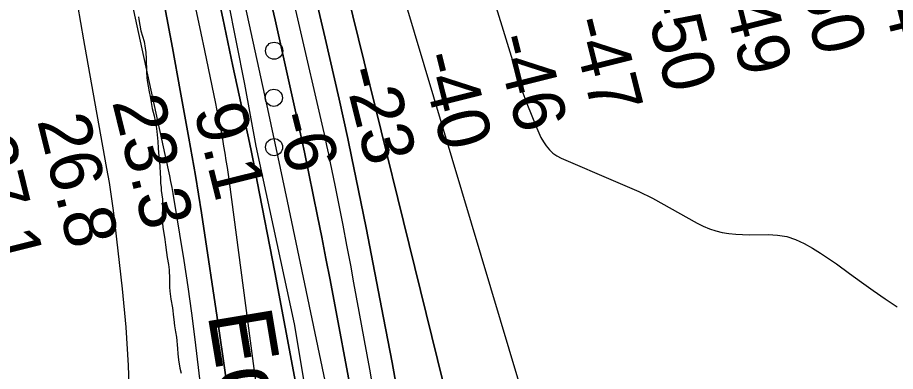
# Model space of a CAD drawing. Extents: x 3250478 to 3288318, y 788638 to 816472.
# Drawn here: x 3274100 to 3275236, y 806350 to 806808 of the extents above; entities that cross this region are included whole.
import ezdxf

# ---------------------------------------------------------------- set-up
doc = ezdxf.new("R2010")
doc.units = 0
for name, color, linetype in [('V-ANNO-SYMB', 7, 'Continuous'), ('V-RIVR-EDGE', 7, 'Continuous'), ('V-RIVR-IDEN', 7, 'Continuous'), ('V-RIVR-RANG', 7, 'Continuous'), ('V-SITE-VEGE', 7, 'Continuous'), ('V-TOPO-DPTH', 7, 'Continuous'), ('V-TOPO-MAJR', 7, 'Continuous'), ('V-TOPO-MINR', 7, 'Continuous'), ('V-TOPO-WATR', 7, 'Continuous')]:
    doc.layers.add(name, color=color, linetype=linetype)

msp = doc.modelspace()

# ---------------------------------------------------------------- linework, layer by layer
at = {"layer": 'V-ANNO-SYMB'}
for centre in [(3274431.8095558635, 806765.4957831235), (3274431.418346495, 806704.615252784), (3274431.7732697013, 806640.7464983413)]:
    msp.add_circle(centre, 11.10590807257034, dxfattribs=at)
at = {"layer": 'V-RIVR-EDGE'}
msp.add_lwpolyline([(3274372.0164002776, 806831.2774582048), (3274393.4804442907, 806722.1199082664), (3274408.0616774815, 806642.1028829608), (3274457.9155695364, 806412.0343195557), (3274469.051635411, 806345.0661887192), (3274504.142647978, 806121.5543174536), (3274513.578701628, 806070.2388409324), (3274547.7466196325, 805824.9952929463), (3274554.1711076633, 805786.2929595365), (3274589.6376810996, 805538.8728044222), (3274595.179918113, 805494.9565023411), (3274635.0040051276, 805251.8723642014), (3274642.658359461, 805183.174125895), (3274676.309913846, 804904.8962366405), (3274682.3050995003, 804868.3683606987), (3274707.6935005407, 804588.3721871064)], dxfattribs=at)
at = {"layer": 'V-SITE-VEGE'}
msp.add_lwpolyline([(3274256.3850000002, 806809.282), (3274256.786, 806806.054), (3274259.508, 806791.061), (3274263.6350000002, 806777.421), (3274265.091, 806768.889), (3274265.681, 806763.359), (3274266.218, 806754.844), (3274266.615, 806738.282), (3274267.166, 806730.454), (3274267.973, 806724.232), (3274270.06, 806712.237), (3274271.3310000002, 806706.237), (3274274.041, 806690.5530000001), (3274276.4, 806681.085), (3274277.662, 806674.394), (3274279.151, 806667.701), (3274279.947, 806660.787), (3274281.098, 806648.123), (3274281.6350000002, 806639.376), (3274282.227, 806633.846), (3274283.98, 806616.112), (3274284.267, 806606.448), (3274284.631, 806601.154), (3274284.965, 806594.0210000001), (3274285.555, 806588.491), (3274285.717, 806584.579), (3274287.355, 806573.285), (3274287.486, 806567.763), (3274287.111, 806546.8470000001), (3274287.631, 806537.18), (3274290.3310000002, 806521.0380000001), (3274291.127, 806514.126), (3274292.559, 806504.214), (3274293.593, 806497.756), (3274295.272, 806488.76), (3274296.073, 806482.079), (3274296.5500000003, 806470.112), (3274296.591, 806459.537), (3274296.727, 806454.247), (3274297.921, 806443.878), (3274300.247, 806432.569), (3274301.414, 806420.5920000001), (3274302.051, 806417.5920000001), (3274303.057, 806409.527), (3274304.292, 806401.457), (3274305.553, 806394.767), (3274306.899, 806380.027), (3274307.235, 806373.123), (3274308.019, 806365.5210000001), (3274309.666, 806354.685), (3274311.39, 806348.218)], dxfattribs=at)
at = {"layer": 'V-TOPO-DPTH'}
for points in [[(3272896.8718829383, 811666.7885982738), (3273467.3050510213, 810068.0688245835), (3273725.425261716, 809243.5940511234), (3273978.688410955, 808646.7703251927), (3274258.488397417, 807822.2419438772), (3274387.5351008, 807404.5846132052), (3274650.472167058, 806336.1989603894), (3274951.6704880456, 805397.7981484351), (3275222.5651054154, 804691.4067671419)], [(3275222.5651054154, 804691.4067671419), (3274951.6704880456, 805397.7981484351), (3274650.472167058, 806336.1989603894), (3274387.5351008, 807404.5846132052), (3274258.488397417, 807822.2419438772), (3273978.688410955, 808646.7703251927), (3273725.425261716, 809243.5940511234), (3273467.3050510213, 810068.0688245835), (3272896.8718829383, 811666.7885982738)], [(3274617.4222593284, 805491.1386361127), (3274604.2925982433, 805560.98414393), (3274590.6944715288, 805630.7440241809), (3274541.090595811, 805878.5779743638), (3274536.753836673, 805900.6834834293), (3274532.52971438, 805922.8100506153), (3274528.474547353, 805944.9682049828), (3274524.5320171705, 805967.1474174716), (3274485.1562987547, 806193.672837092), (3274472.5268671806, 806265.1076904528), (3274459.6231666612, 806336.4921489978), (3274446.3080627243, 806407.8010153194), (3274432.718689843, 806479.0594868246), (3274410.000424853, 806596.348323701), (3274407.5280961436, 806608.917167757), (3274405.0072768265, 806621.4761325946), (3274402.4137216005, 806634.0202786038), (3274399.7716757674, 806646.5545453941), (3274378.5716780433, 806745.7061613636), (3274365.266387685, 806807.8030393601), (3274351.9252642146, 806869.892201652)], [(3274351.9252642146, 806869.892201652), (3274365.266387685, 806807.8030393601), (3274378.5716780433, 806745.7061613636), (3274399.7716757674, 806646.5545453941), (3274402.4137216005, 806634.0202786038), (3274405.0072768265, 806621.4761325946), (3274407.5280961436, 806608.917167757), (3274410.000424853, 806596.348323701), (3274432.718689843, 806479.0594868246), (3274446.3080627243, 806407.8010153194), (3274459.6231666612, 806336.4921489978), (3274472.5268671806, 806265.1076904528), (3274485.1562987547, 806193.672837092), (3274524.5320171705, 805967.1474174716), (3274528.474547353, 805944.9682049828), (3274532.52971438, 805922.8100506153), (3274536.753836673, 805900.6834834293), (3274541.090595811, 805878.5779743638), (3274590.6944715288, 805630.7440241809), (3274604.2925982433, 805560.98414393), (3274617.4222593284, 805491.1386361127)], [(3274688.1484999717, 805434.1228253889), (3274676.465678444, 805507.2707436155), (3274664.4258522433, 805580.3607487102), (3274652.1480229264, 805653.4121450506), (3274608.4767440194, 805909.4249769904), (3274606.0971900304, 805923.1733139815), (3274603.6732208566, 805936.9137044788), (3274601.1826289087, 805950.6421752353), (3274598.647621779, 805964.3626994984), (3274504.183789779, 806468.78976013), (3274498.939337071, 806496.4099469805), (3274493.602246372, 806524.0119793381), (3274488.126198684, 806551.5867799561), (3274482.557513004, 806579.1434260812), (3274476.8515547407, 806606.6719972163), (3274471.0552148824, 806634.1812916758), (3274465.1233026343, 806661.6616711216), (3274459.1010087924, 806689.1227738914), (3274452.270295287, 806719.9072703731), (3274442.7205471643, 806762.7361712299), (3274433.111722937, 806805.5517497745), (3274423.414284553, 806848.347344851)], [(3274423.414284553, 806848.347344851), (3274433.111722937, 806805.5517497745), (3274442.7205471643, 806762.7361712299), (3274452.270295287, 806719.9072703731), (3274459.1010087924, 806689.1227738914), (3274465.1233026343, 806661.6616711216), (3274471.0552148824, 806634.1812916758), (3274476.8515547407, 806606.6719972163), (3274482.557513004, 806579.1434260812), (3274488.126198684, 806551.5867799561), (3274493.602246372, 806524.0119793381), (3274498.939337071, 806496.4099469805), (3274504.183789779, 806468.78976013), (3274598.647621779, 805964.3626994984), (3274601.1826289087, 805950.6421752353), (3274603.6732208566, 805936.9137044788), (3274606.0971900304, 805923.1733139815), (3274608.4767440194, 805909.4249769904), (3274652.1480229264, 805653.4121450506), (3274664.4258522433, 805580.3607487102), (3274676.465678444, 805507.2707436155), (3274688.1484999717, 805434.1228253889)], [(3274482.658444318, 806846.3303660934), (3274497.777227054, 806781.6377285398), (3274515.898992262, 806702.7509565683), (3274521.609837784, 806677.4201953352), (3274527.18336579, 806652.0598389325), (3274532.5509175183, 806626.6550897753), (3274537.781151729, 806601.2207454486), (3274550.895423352, 806536.1087825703), (3274562.380969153, 806478.0585651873), (3274573.601449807, 806419.9580974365), (3274584.4243327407, 806361.7822541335), (3274594.9821505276, 806303.5561604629)], [(3274594.9821505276, 806303.5561604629), (3274584.4243327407, 806361.7822541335), (3274573.601449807, 806419.9580974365), (3274562.380969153, 806478.0585651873), (3274550.895423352, 806536.1087825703), (3274537.781151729, 806601.2207454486), (3274532.5509175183, 806626.6550897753), (3274527.18336579, 806652.0598389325), (3274521.609837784, 806677.4201953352), (3274515.898992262, 806702.7509565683), (3274497.777227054, 806781.6377285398), (3274482.658444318, 806846.3303660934)], [(3274600.483922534, 806832.0100823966), (3274859.3268003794, 805965.620046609)], [(3274600.483922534, 806832.0100823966), (3274859.3268003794, 805965.620046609)], [(3274478.8771368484, 805483.1582757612), (3274468.908506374, 805558.2114425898), (3274459.40646076, 805633.3287982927), (3274432.7241389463, 805852.4702170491), (3274429.869571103, 805875.8581771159), (3274427.0059573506, 805899.2450268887), (3274424.1287747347, 805922.6302112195), (3274421.2425462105, 805946.0142852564), (3274406.234731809, 806067.3173524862), (3274395.5255796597, 806151.3095590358), (3274384.4001715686, 806235.2450150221), (3274372.650379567, 806319.0953451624), (3274360.4843316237, 806402.8889247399), (3274337.7003442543, 806555.8091983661), (3274333.967639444, 806580.0158876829), (3274330.070924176, 806604.1952878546), (3274325.928193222, 806628.3337543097), (3274321.62145181, 806652.4449316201), (3274310.2803518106, 806714.1218491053), (3274300.174531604, 806769.0500017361), (3274290.061389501, 806823.9768055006)]]:
    msp.add_lwpolyline(points, dxfattribs=at)
at = {"layer": 'V-TOPO-MAJR'}
msp.add_lwpolyline([(3274653.0490446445, 807036.1317875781), (3274749.1714196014, 806725.0046189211), (3274751.4288745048, 806717.9909878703), (3274753.795132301, 806711.0156974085), (3274756.3245944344, 806704.09791783), (3274758.962859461, 806697.2184788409), (3274771.7233760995, 806665.0792478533), (3274774.3330273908, 806659.1308457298), (3274777.2116374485, 806653.3279504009), (3274780.4936856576, 806647.7433152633), (3274784.044692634, 806642.3041869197), (3274788.149218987, 806637.4056710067), (3274792.691259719, 806633.0457846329), (3274797.889572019, 806629.493842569), (3274803.5253986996, 806626.4805300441), (3274873.8457806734, 806596.1319161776), (3274879.850851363, 806593.550086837), (3274885.8606333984, 806590.979313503), (3274891.8774824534, 806588.4251241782), (3274897.899042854, 806585.8819908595), (3274903.877212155, 806583.250712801), (3274909.7929705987, 806580.4911715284), (3274915.6151127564, 806577.5392354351), (3274921.374844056, 806574.4590361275), (3274979.4019049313, 806542.1927834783), (3274987.202726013, 806538.3362342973), (3274995.1926584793, 806535.0024433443), (3275003.466258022, 806532.452789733), (3275011.9289689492, 806530.4258943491), (3275020.559471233, 806529.0603622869), (3275029.2202377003, 806528.039723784), (3275037.926400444, 806527.5364256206), (3275046.662827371, 806527.3780210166), (3275071.240764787, 806527.6653365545), (3275083.397129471, 806526.8684873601), (3275095.2592614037, 806524.8818654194), (3275106.6800442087, 806521.1105843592), (3275117.8065942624, 806516.1495305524), (3275128.562964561, 806510.0303936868), (3275139.136987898, 806503.6238546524), (3275149.437490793, 806496.7862123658), (3275159.555646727, 806489.6611679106), (3275176.636735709, 806477.0971207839), (3275191.858120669, 806466.0672731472), (3275207.1818678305, 806455.1837465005), (3275222.6591582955, 806444.5197013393), (3275238.238810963, 806434.0019771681)], dxfattribs=at)
at = {"layer": 'V-TOPO-MINR'}
for points in [[(3275222.5651054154, 804691.4067671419), (3274951.6704880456, 805397.7981484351), (3274650.472167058, 806336.1989603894), (3274387.5351008, 807404.5846132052), (3274258.488397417, 807822.2419438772), (3273978.688410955, 808646.7703251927), (3273725.425261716, 809243.5940511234), (3273467.3050510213, 810068.0688245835), (3272896.8718829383, 811666.7885982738)], [(3274240.7163674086, 807239.4246731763), (3274336.80832049, 806788.4476416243), (3274341.6362212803, 806765.6026163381), (3274346.4132960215, 806742.7470562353), (3274351.1141316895, 806719.8756939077), (3274355.764141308, 806696.9937967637), (3274361.305373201, 806669.4914699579), (3274363.0958192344, 806660.343567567), (3274364.818515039, 806651.183312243), (3274366.4395854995, 806642.0045275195), (3274367.9929057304, 806632.8133898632), (3274369.4534120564, 806623.6067806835), (3274370.8579467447, 806614.3919008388), (3274372.1785239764, 806605.1646149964), (3274373.4431295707, 806595.9290584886), (3274445.223089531, 806053.3452152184)], [(3274331.095173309, 807113.8194124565), (3274424.5356362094, 806684.1983500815), (3274430.658804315, 806655.8941987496), (3274436.7401236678, 806627.5811073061), (3274442.7586698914, 806599.2546056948), (3274448.735367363, 806570.9191639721), (3274554.090815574, 806068.6746532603), (3274558.7520225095, 806046.1547194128), (3274563.332903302, 806023.6186811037), (3274567.7932948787, 806001.0584861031), (3274572.173360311, 805978.4821866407), (3274579.93956688, 805937.8725912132), (3274580.369125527, 805935.5877191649), (3274580.7891451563, 805933.3011257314), (3274581.1948562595, 805931.0119502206), (3274581.591028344, 805928.7210533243), (3274586.8087218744, 805897.9770770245), (3274589.762691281, 805880.3058243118), (3274592.6581379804, 805862.6251367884), (3274595.4658006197, 805844.9302970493), (3274598.2149405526, 805827.2260224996), (3274685.068318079, 805258.5934466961)], [(3274432.045237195, 806938.1293400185), (3274494.7991760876, 806665.0588884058), (3274497.310896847, 806653.9430920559), (3274499.7682875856, 806642.8155059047), (3274502.1441832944, 806631.6702350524), (3274504.4657489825, 806620.5131743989), (3274510.428507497, 806591.3220104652), (3274515.616674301, 806565.546139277), (3274520.706147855, 806539.7510893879), (3274525.647581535, 806513.9272714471), (3274530.4903219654, 806488.0842748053), (3274534.7111053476, 806465.1979394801), (3274541.5681571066, 806427.8933675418), (3274548.395802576, 806390.583432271), (3274555.1793386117, 806353.2654520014), (3274561.933468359, 806315.9421083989), (3274619.970834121, 805994.1420670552), (3274624.72713484, 805967.5666837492), (3274629.4360971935, 805940.982980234), (3274634.0740519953, 805914.3867964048), (3274638.6646684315, 805887.7822923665), (3274727.84656241, 805366.7859836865)], [(3274231.8357465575, 806901.3451004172), (3274294.739013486, 806611.32062441), (3274296.3321274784, 806603.7177424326), (3274297.853764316, 806596.1011026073), (3274299.2681854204, 806588.4638260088), (3274300.61112937, 806580.8127915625), (3274309.4762218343, 806528.1345675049), (3274314.9525415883, 806494.0988075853), (3274320.1016340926, 806460.0160164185), (3274324.7598857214, 806425.8626783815), (3274329.0909101, 806391.6623090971), (3274387.919728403, 805898.6871207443), (3274388.3923747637, 805894.703242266), (3274388.861382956, 805890.7189380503), (3274389.324933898, 805886.7339952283), (3274389.7848466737, 805882.7486266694), (3274392.703112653, 805857.3074612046), (3274394.6471255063, 805840.6045227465), (3274396.628065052, 805823.9060270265), (3274398.6643946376, 805807.2141954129), (3274400.737650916, 805790.5268065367), (3274472.088332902, 804733.2881120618)], [(3274173.3374492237, 806847.1647750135), (3274184.982310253, 806779.5539544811), (3274197.02545191, 806712.0099221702), (3274215.0802471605, 806613.2740282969), (3274218.205554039, 806595.1201670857), (3274221.07884344, 806576.9291748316), (3274223.574106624, 806558.6824860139), (3274225.8173523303, 806540.3986661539), (3274235.152795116, 806457.1736840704), (3274239.743368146, 806407.6212667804), (3274243.054813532, 806358.0082629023), (3274244.4475674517, 806308.3043791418)], [(3274423.414284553, 806848.347344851), (3274433.111722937, 806805.5517497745), (3274442.7205471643, 806762.7361712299), (3274452.270295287, 806719.9072703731), (3274459.1010087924, 806689.1227738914), (3274465.1233026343, 806661.6616711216), (3274471.0552148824, 806634.1812916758), (3274476.8515547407, 806606.6719972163), (3274482.557513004, 806579.1434260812), (3274488.126198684, 806551.5867799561), (3274493.602246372, 806524.0119793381), (3274498.939337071, 806496.4099469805), (3274504.183789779, 806468.78976013), (3274598.647621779, 805964.3626994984), (3274601.1826289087, 805950.6421752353), (3274603.6732208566, 805936.9137044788), (3274606.0971900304, 805923.1733139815), (3274608.4767440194, 805909.4249769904), (3274652.1480229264, 805653.4121450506), (3274664.4258522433, 805580.3607487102), (3274676.465678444, 805507.2707436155), (3274688.1484999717, 805434.1228253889)], [(3274482.658444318, 806846.3303660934), (3274497.777227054, 806781.6377285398), (3274515.898992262, 806702.7509565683), (3274521.609837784, 806677.4201953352), (3274527.18336579, 806652.0598389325), (3274532.5509175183, 806626.6550897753), (3274537.781151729, 806601.2207454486), (3274550.895423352, 806536.1087825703), (3274562.380969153, 806478.0585651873), (3274573.601449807, 806419.9580974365), (3274584.4243327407, 806361.7822541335), (3274594.9821505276, 806303.5561604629)], [(3274600.483922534, 806832.0100823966), (3274859.3268003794, 805965.620046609)], [(3274290.061389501, 806823.9768055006), (3274300.174531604, 806769.0500017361), (3274310.2803518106, 806714.1218491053), (3274321.62145181, 806652.4449316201), (3274325.928193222, 806628.3337543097), (3274330.070924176, 806604.1952878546), (3274333.967639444, 806580.0158876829), (3274337.7003442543, 806555.8091983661), (3274360.4843316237, 806402.8889247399), (3274372.650379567, 806319.0953451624), (3274384.4001715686, 806235.2450150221), (3274395.5255796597, 806151.3095590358), (3274406.234731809, 806067.3173524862), (3274421.2425462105, 805946.0142852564), (3274424.1287747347, 805922.6302112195), (3274427.0059573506, 805899.2450268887), (3274429.869571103, 805875.8581771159), (3274432.7241389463, 805852.4702170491), (3274459.40646076, 805633.3287982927), (3274468.908506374, 805558.2114425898), (3274478.8771368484, 805483.1582757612)]]:
    msp.add_lwpolyline(points, dxfattribs=at)
at = {"layer": 'V-TOPO-WATR'}
msp.add_lwpolyline([(3274351.9252642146, 806869.892201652), (3274365.266387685, 806807.8030393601), (3274378.5716780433, 806745.7061613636), (3274399.7716757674, 806646.5545453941), (3274402.4137216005, 806634.0202786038), (3274405.0072768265, 806621.4761325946), (3274407.5280961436, 806608.917167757), (3274410.000424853, 806596.348323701), (3274432.718689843, 806479.0594868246), (3274446.3080627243, 806407.8010153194), (3274459.6231666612, 806336.4921489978), (3274472.5268671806, 806265.1076904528), (3274485.1562987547, 806193.672837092), (3274524.5320171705, 805967.1474174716), (3274528.474547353, 805944.9682049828), (3274532.52971438, 805922.8100506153), (3274536.753836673, 805900.6834834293), (3274541.090595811, 805878.5779743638), (3274590.6944715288, 805630.7440241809), (3274604.2925982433, 805560.98414393), (3274617.4222593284, 805491.1386361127)], dxfattribs=at)

# ---------------------------------------------------------------- texts
at = {"layer": 'V-RIVR-IDEN'}
msp.add_text('Edge', height=82.99999999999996, rotation=279.4412690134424, dxfattribs=at).set_placement((3274345.4775154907, 806424.6576978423))
at = {"layer": 'V-RIVR-RANG'}
for s, rotation, p in [('-54', 284.1189444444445, (3275200.953035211, 806904.9087354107)), ('-50', 284.1189444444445, (3275103.691654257, 806881.6369798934)), ('-49', 284.1189444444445, (3275007.4597971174, 806854.2722464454)), ('-50', 284.1189444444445, (3274909.6846542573, 806833.0459798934)), ('-47', 284.1189444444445, (3274813.964677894, 806803.6462117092)), ('-46', 284.1189444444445, (3274716.3844518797, 806781.6420575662)), ('-40', 284.1189444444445, (3274619.1874161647, 806758.1144909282)), ('-23', 284.1189444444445, (3274520.8321661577, 806739.1915244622)), ('23.3', 283.91832571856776, (3274221.894463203, 806699.5206443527)), ('9.1', 283.91832571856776, (3274327.4640962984, 806689.25093904)), ('26.8', 283.91832571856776, (3274124.891463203, 806675.2256443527)), ('-6', 284.1189444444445, (3274432.4504281, 806680.6178342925)), ('27.1', 283.91832571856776, (3274028.4585054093, 806648.6263306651))]:
    msp.add_text(s, height=67, rotation=rotation, dxfattribs=at).set_placement(p)

doc.saveas('drawing.dxf')
